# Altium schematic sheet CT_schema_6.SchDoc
size 373 x 336 mm
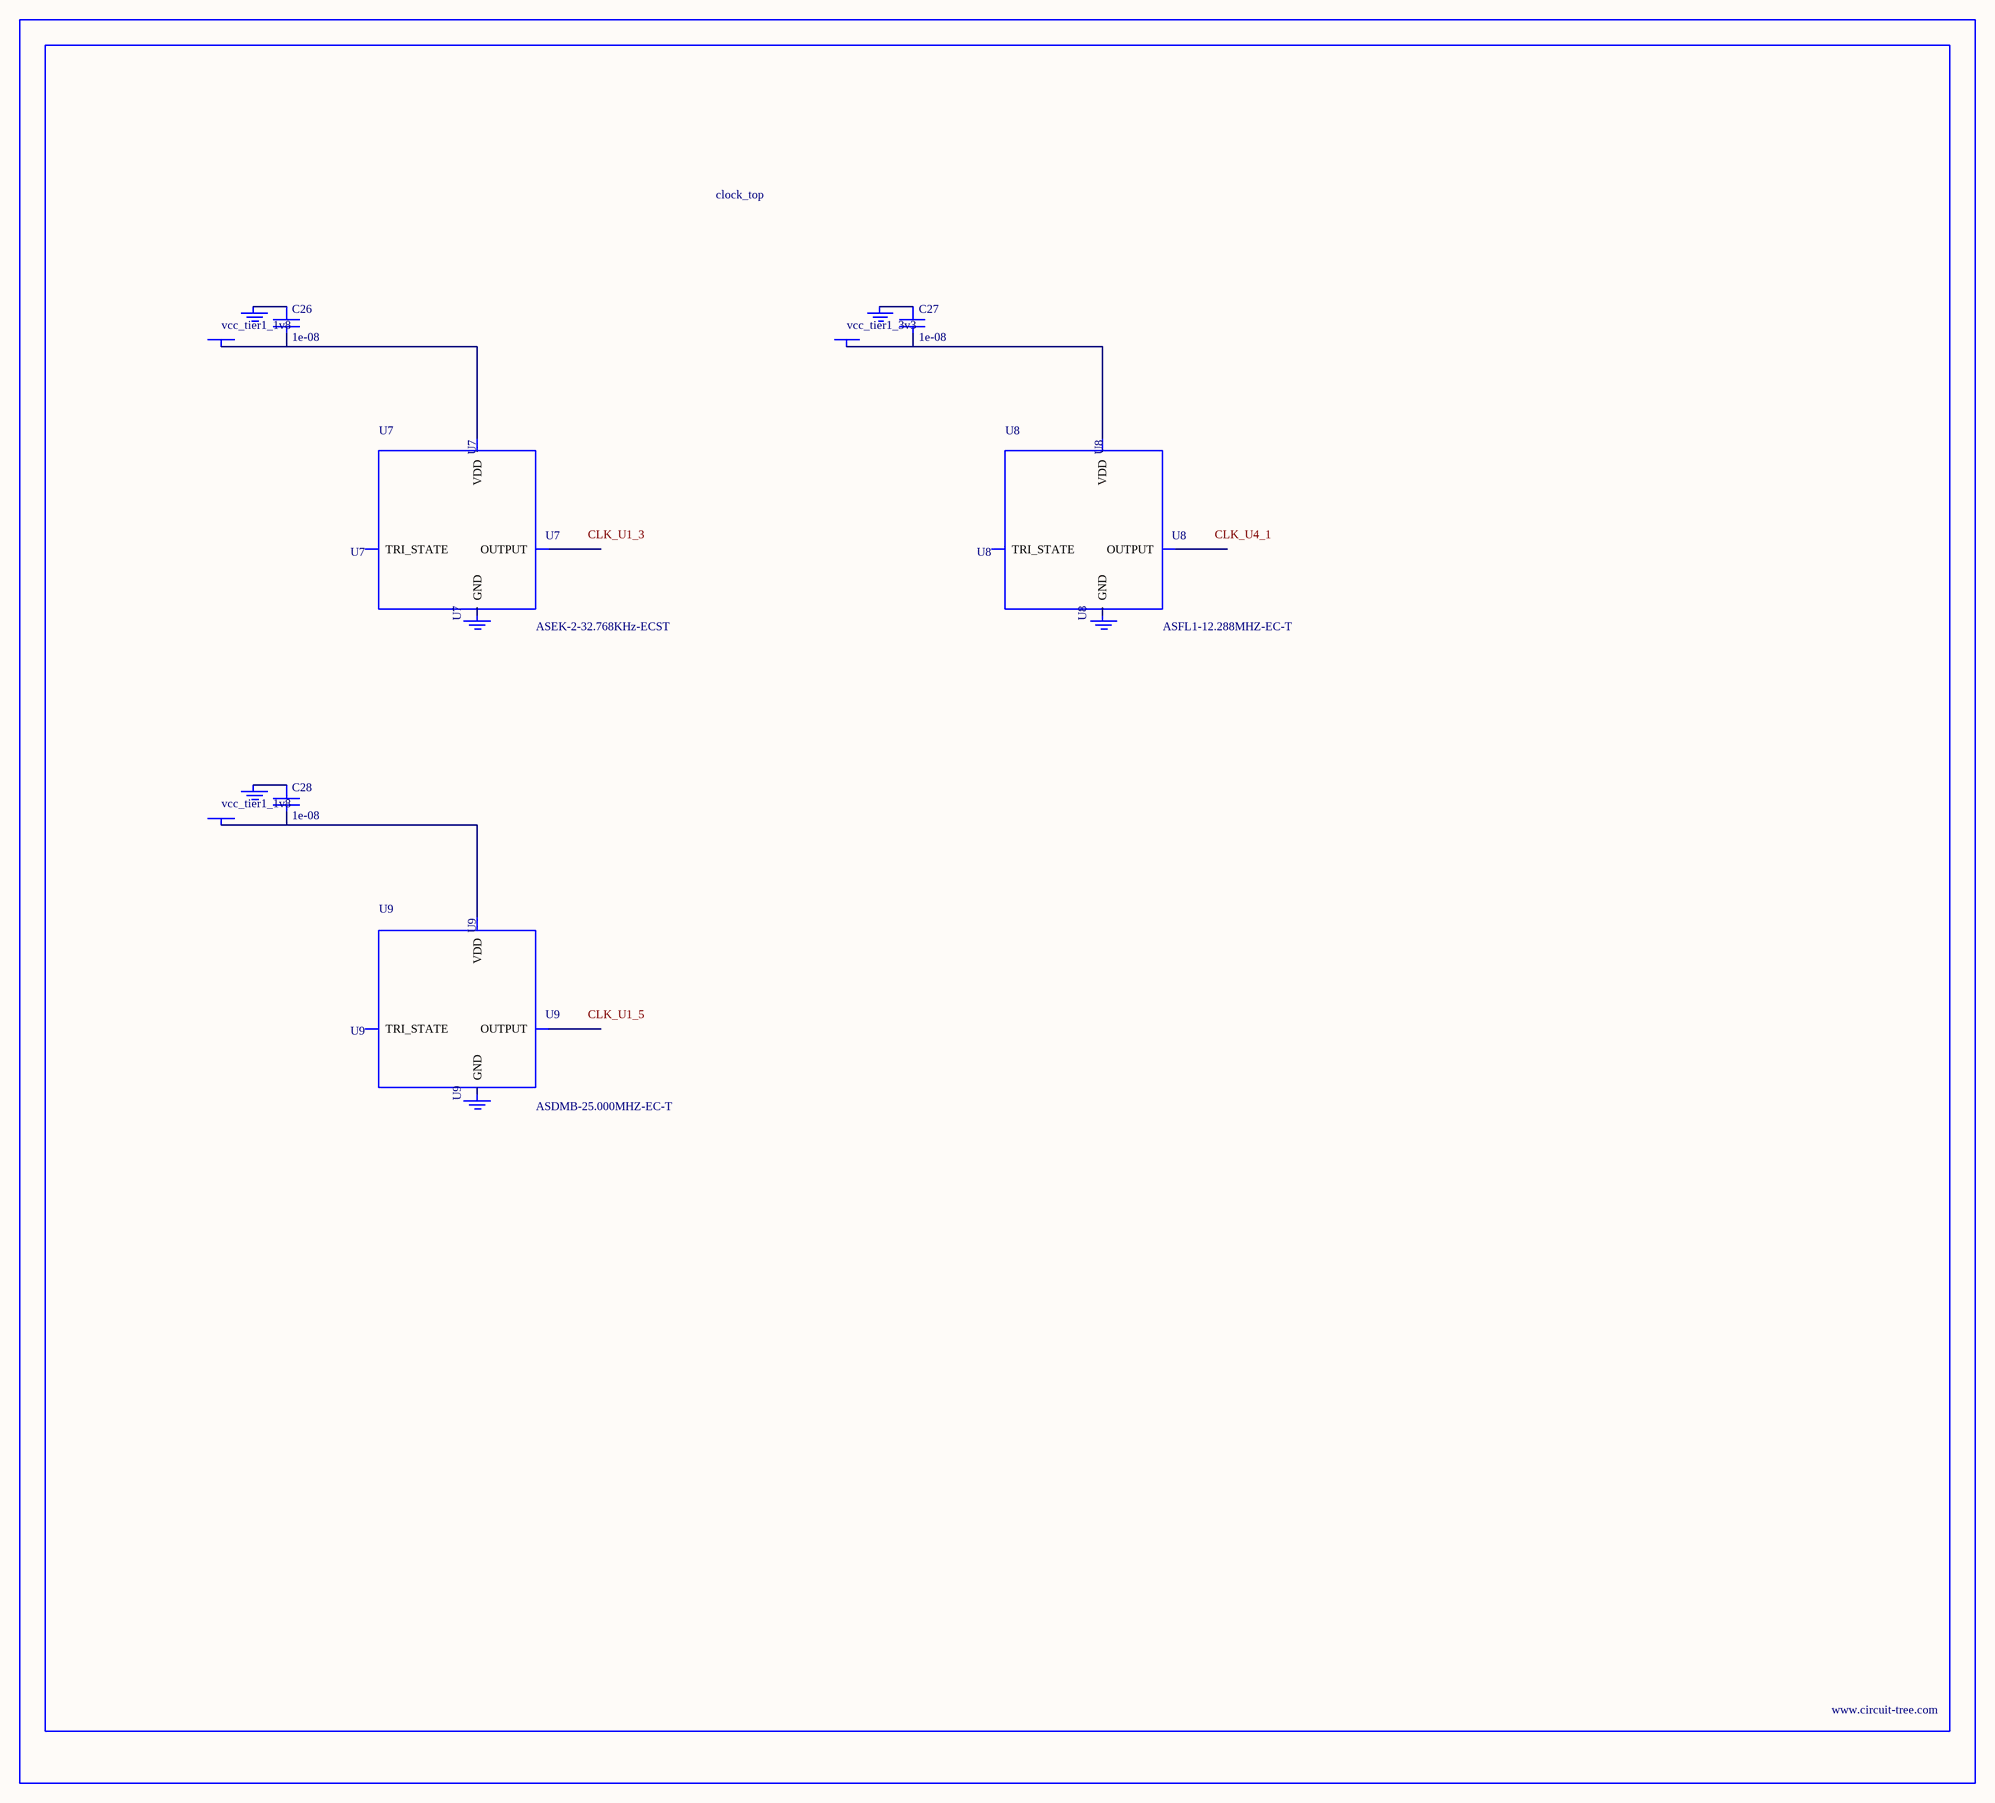
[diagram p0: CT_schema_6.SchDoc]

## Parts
BORDER5  (no value)
C26  1e-08  [C0402]
C27  1e-08  [C0402]
C28  1e-08  [C0402]
GND_INSTANCE_5_0  (no value)
GND_INSTANCE_5_1  (no value)
GND_INSTANCE_5_2  (no value)
GND_INSTANCE_5_3  (no value)
GND_INSTANCE_5_4  (no value)
GND_INSTANCE_5_5  (no value)
POWER_INSTANCE_5_0  vcc_tier1_1v8
POWER_INSTANCE_5_1  vcc_tier1_3v3
POWER_INSTANCE_5_2  vcc_tier1_1v8
U7  ASEK-2-32.768KHz-ECST  [ASEK]
U8  ASFL1-12.288MHZ-EC-T  [ASFL1]
U9  ASDMB-25.000MHZ-EC-T  [ASDMB-XX.XXXXMHZ-XX-XX-XXX]

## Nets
NetC26_1: C26.1 GND_INSTANCE_5_0.0(GND)
NetC26_2: C26.2 POWER_INSTANCE_5_0.0(PWR) U7.4(VDD)
NetC27_1: C27.1 GND_INSTANCE_5_2.0(GND)
NetC27_2: C27.2 POWER_INSTANCE_5_1.0(PWR) U8.4(VDD)
NetC28_1: C28.1 GND_INSTANCE_5_4.0(GND)
NetC28_2: C28.2 POWER_INSTANCE_5_2.0(PWR) U9.4(VDD)

Not connected (* = marked no-connect by the designer): GND_INSTANCE_5_1 0(GND); GND_INSTANCE_5_3 0(GND); GND_INSTANCE_5_5 0(GND); U7 1(TRI_STATE) 2(GND) 3(OUTPUT); U8 1(TRI_STATE) 2(GND) 3(OUTPUT); U9 1(TRI_STATE) 2(GND) 3(OUTPUT)

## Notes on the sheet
- Labels drawn without touching a wire or pin: CLK_U1_3, CLK_U1_5, CLK_U4_1

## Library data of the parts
BORDER5 = BORDER_PAGE5
C26-C28 = C0402C103K3RAC
GND_INSTANCE_5_0-GND_INSTANCE_5_5 = GND
POWER_INSTANCE_5_0-POWER_INSTANCE_5_2 = PWR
